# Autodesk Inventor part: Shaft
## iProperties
Created: 2007-11
Part Number: Shaft
Material: Steel
Document SubType Name: Modeling
Designer: CM
Density: 7.85 g/cm^3
Mass: 744.543 g
Surface Area: 152.39 cm^2
Volume: 94.8463 cm^3
CustomPartVersion: 1
Author: CM
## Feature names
1. Revolution1
2. Chamfer1
3. Chamfer2
4. Chamfer3
5. Fillet1
6. Chamfer4
7. Chamfer5
